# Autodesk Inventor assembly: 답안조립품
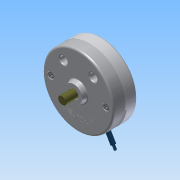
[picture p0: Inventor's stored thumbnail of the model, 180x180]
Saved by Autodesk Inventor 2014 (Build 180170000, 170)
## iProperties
Created: 2015-06
Part Number: 답안조립품
Document SubType Name: Assembly
Designer: Administrator
Author: Administrator
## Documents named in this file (10)
- C:\Documents and Settings\Administrator\바탕 화면\450631V1028\답안조립품.iam
- C:\Documents and Settings\Administrator\바탕 화면\450631V1028\1-본체.ipt
- C:\Documents and Settings\Administrator\바탕 화면\450631V1028\베어링62_22.ipt
- C:\Documents and Settings\Administrator\바탕 화면\450631V1028\축.ipt
- C:\Documents and Settings\Administrator\바탕 화면\450631V1028\멈춤링.ipt
- C:\Documents and Settings\Administrator\바탕 화면\450631V1028\덮개.ipt
- C:\Documents and Settings\Administrator\바탕 화면\450631V1028\M10x35.ipt
- C:\Documents and Settings\Administrator\바탕 화면\450631V1028\슬라이더.ipt
- C:\Documents and Settings\Administrator\바탕 화면\450631V1028\슬라이더2.ipt
- C:\Documents and Settings\Administrator\바탕 화면\450631V1028\평행핀.ipt
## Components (8 placed, 5 different names)
1. 1-본체:1 — 각도:1
2. KS B 2023 62/22 - 22 x 50 x 14:1
3. KS B 1336 22 x 1.2:1
4. KS B 1336 22 x 1.2:2
5. KS B 2023 62/22 - 22 x 50 x 14:2
6. KS B 1003 - 미터 M 10 x 35:1
7. KS B 1003 - 미터 M 10 x 35:2
8. KS B 1320 B B 5 x  20:1 — 플러쉬:1
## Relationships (2: Flush 1, Angle 1)
- 플러쉬:1 [Flush]: KS B 1320 B B 5 x  20:1
- 각도:1 [Angle]: 1-본체:1
